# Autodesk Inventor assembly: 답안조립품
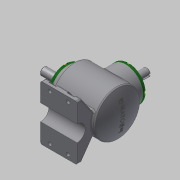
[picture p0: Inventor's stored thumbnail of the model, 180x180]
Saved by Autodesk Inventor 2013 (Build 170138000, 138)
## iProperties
Created: 2017-04
Part Number: 답안조립품
Document SubType Name: Assembly
Designer: Administrator
Author: Administrator
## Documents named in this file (14)
- C:\Users\Administrator\Desktop\470407V1001\답안조립품.iam
- C:\Users\Administrator\Desktop\470407V1001\본체.ipt
- C:\Users\Administrator\Desktop\470407V1001\메인 베벨기어.ipt
- C:\Users\Administrator\Desktop\470407V1001\메인 축.ipt
- 메인 축.ipt
- C:\Users\Administrator\Desktop\470407V1001\베어링 6203.ipt
- C:\Users\Administrator\Desktop\470407V1001\볼트 M4.ipt
- C:\Users\Administrator\Desktop\470407V1001\서브 베벨기어.ipt
- C:\Users\Administrator\Desktop\470407V1001\서브 축.ipt
- 서브 축.ipt
- C:\Users\Administrator\Desktop\470407V1001\오일실 17 32 8.ipt
- C:\Users\Administrator\Desktop\470407V1001\커버.ipt
- C:\Users\Administrator\Desktop\470407V1001\키 4x4.ipt
- C:\Users\Administrator\Desktop\470407V1001\키 5x5.ipt
